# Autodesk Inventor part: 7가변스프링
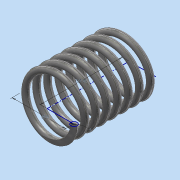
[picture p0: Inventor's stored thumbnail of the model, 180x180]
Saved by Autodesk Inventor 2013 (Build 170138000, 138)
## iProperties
Created: 2014-12
Part Number: 7가변스프링
Material: 강철, 탄소
Document SubType Name: Modeling
Designer: 교육생
Density: 7.87 g/cm^3
Mass: 80.1302 g
Surface Area: 103.216 cm^2
Volume: 10.1817 cm^3
Author: 교육생
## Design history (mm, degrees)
sketch "스케치1"
  geometry: L1 (0, 0)-(17.5, 0); L2 (0, 0)-(0, 48.5); L3 (0, 48.5)-(17.5, 48.5); C1 r 2 at (17.5, 0)
  constraints: 6 end point, 2 perpendicular, 1 centre point, 1 coincident, 1 horizontal, 1 parallel
  dimensions: "d0" = 4 diameter of C1; "d2" = 35 diameter of L1.end L2; "d3" = 48.5 distance of L1.start L2.end (derived)
feature "코일1" sketch "스케치1" pitch "d4" = 10; turns "d6" = 7.5; dims "d5" = 48.50005 (computed from d3), "d7" = 0, angle "d8" = 90 deg, angle "d9" = 90 deg, "d10" = 0, "d11" = 0
node "작업 평면1"
feature "분할1"
feature "분할2"
node "솔리드1"
other parameters: "d12" = 0
